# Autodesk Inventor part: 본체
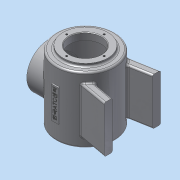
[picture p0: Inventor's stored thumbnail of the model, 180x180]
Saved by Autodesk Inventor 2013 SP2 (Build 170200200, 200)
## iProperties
Created: 2015-01
Part Number: 본체
Material: 알루미늄 6061
Document SubType Name: Modeling
Designer: dgall
Density: 2.71 g/cm^3
Mass: 1021.94 g
Surface Area: 1062.48 cm^2
Volume: 377.099 cm^3
Author: dgall
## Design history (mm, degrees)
sketch "스케치1"
  geometry: C1 r 50 at (0, 0); 1 further point
  constraints: 1 centre point, 1 coincident
  dimensions: "d0" = 100 diameter of C1
extrude "돌출1" new body sketch "스케치1" distance "d2" = 112; taper "d3" = 0 deg
sketch "스케치2"
  geometry: C1 r 50 at (0, 0) reference; C2 r 38 at (0, 0)
  constraints: 1 centre point, 1 coincident
  dimensions: "d4" = 76 diameter of C2
extrude "돌출2" join sketch "스케치2" distance "d6" = 5; taper "d7" = 0 deg
node "작업 평면1"
node "작업 평면2"
sketch "스케치3"
  geometry: L1 (50, 0)-(50, -112) reference; L2 (38, -117)-(-38, -117) reference; C1 r 38 at (0, -55); 1 further point
  constraints: 1 centre point, 1 vertical alignment
  dimensions: "d9" = 76 diameter of C1; "d71" = 62 distance from line of L2 C1.centre
extrude "돌출3" join sketch "스케치3" stored distance "d11" = 10; taper "d12" = 0 deg
node "작업 평면3"
sketch "스케치4"
  geometry: L1 (-30.865, 39.336)-(-80, 48); L2 (-80, 48)-(-80, 34); L3 (-80, 34)-(-30.865, 25.336); L4 (62, 38)-(62, -38) reference; L5 (-30.865, 39.336)-(-30.865, 25.336); 2 further points
  constraints: 8 end point, 2 parallel, 1 vertical, 1 vertical alignment, 2 other
  dimensions: "d13" = 48 vertical distance of point (0, 0) L1.end; "d14" = 100 deg angle of L2 L1; "d15" = 142 distance between parallel lines of L2 L4; "d16" = 14 distance of L1.end L2.end
extrude "돌출4" join sketch "스케치4" stored distance "d17" = 80; taper "d18" = 0 deg
sketch "스케치6"
  geometry: C1 r 38 at (0, 0) reference; C2 r 27 at (0, 0)
  constraints: 1 centre point, 1 coincident
  dimensions: "d19" = 54 diameter of C2
extrude "돌출5" cut sketch "스케치6" distance "d21" = 13; taper "d22" = 0 deg
sketch "스케치7"
  geometry: C1 r 27 at (0, 0) reference; C2 r 45 at (0, 0)
  constraints: 1 centre point, 1 coincident
  dimensions: "d23" = 90 diameter of C2
extrude "돌출6" cut sketch "스케치7" distance "d25" = 97; taper "d26" = 0 deg
sketch "스케치8" dims "d27" = 64
  geometry: C1 r 27 at (0, 0) reference; C2 r 38 at (0, 0) reference; 2 further points
  constraints: 2 horizontal alignment, 1 coincident, 2 other
hole "구멍1" sketch "스케치8" at (32, 0) diameter "d29" = 3.242; stored, may be unused: countersink angle "d33" = 90 deg, drill point angle "d35" = 118 deg; dims "d30" = 8, "d31" = 4, "d32" = 2, "d34" = 10
sketch "스케치9"
  geometry: C1 r 38 at (0, 0) reference; C2 r 27 at (0, 0); 1 further point
  constraints: 1 centre point, 1 coincident
  dimensions: "d39" = 54 diameter of C2
extrude "돌출7" cut sketch "스케치9" stored distance "d41" = 97; taper "d42" = 0 deg
sketch "스케치10" dims "d43" = 64
  geometry: C1 r 27 at (0, 0) reference; C2 r 38 at (0, 0) reference; 3 further points
  constraints: 2 vertical alignment, 1 coincident, 2 other
hole "구멍2" sketch "스케치10" at (0, 32) diameter "d45" = 3.242; stored, may be unused: countersink angle "d49" = 90 deg, drill point angle "d51" = 118 deg; dims "d46" = 8, "d47" = 4, "d48" = 2, "d50" = 10
node "작업 평면4"
sketch "스케치11"
  geometry: L1 (-50, 0)-(-50, -112) reference; L2 (50, 0)-(50, -112) reference; L3 (-6, -83)-(6, -83); L4 (6, -83)-(6, -29); L5 (6, -29)-(-6, -29); L6 (-6, -29)-(-6, -83); L7 (-50, -112)-(50, -112) reference; L8 (-50, 0)-(50, 0) reference; 5 further points
  constraints: 8 end point, 4 midpoint, 2 parallel, 1 horizontal, 1 horizontal alignment, 1 perpendicular, 1 vertical alignment
  dimensions: "d56" = 54 distance of L5.end L3.start; "d58" = 12 distance of L3.start L3.end
extrude "돌출8" join sketch "스케치11" stored distance "d59" = 97; taper "d60" = 0 deg
sketch "스케치12" dims "d37" = 360 deg
  geometry: L1 (-6, -83)-(6, -83) reference; L2 (-50, 0)-(-50, -112) reference; L3 (-62, -93)-(-62, -17) reference; 4 further points
  constraints: 2 midpoint, 1 horizontal alignment, 1 vertical alignment, 1 other
feature "엠보싱1" sketch "스케치12" dims "d12" = 0, "d61" = 0.5, "d62" = 0
fillet "모깎기1" dims "d63" = 3
chamfer "모따기1" distance "d65" = 1; stored, may be unused: second distance "d66" = 2, angle "d67" = 45 deg
fillet "모깎기3" dims "d68" = 3
fillet "모깎기4" dims "d69" = 3
fillet "모깎기5" dims "d70" = 3
fillet "모깎기6" dims "d72" = 3
sketch "스케치14"
  geometry: C1 r 38 at (0, 0) reference; C2 r 27 at (0, 0)
  constraints: 1 centre point, 1 coincident
  dimensions: "d73" = 54 diameter of C2
extrude "돌출9" cut sketch "스케치14" distance "d75" = 12; taper "d76" = 0 deg
chamfer "모따기2" distance "d77" = 1; stored, may be unused: second distance "d78" = 2, angle "d79" = 45 deg
node "솔리드1"
mirror "대칭1"
mirror "대칭2"
pattern_circular "원형 패턴1" dims angle "d37" = 360 deg
mirror "대칭4"
pattern_circular "원형 패턴2" dims angle "d53" = 360 deg
other parameters: "d8" = -62, "d55" = -52
